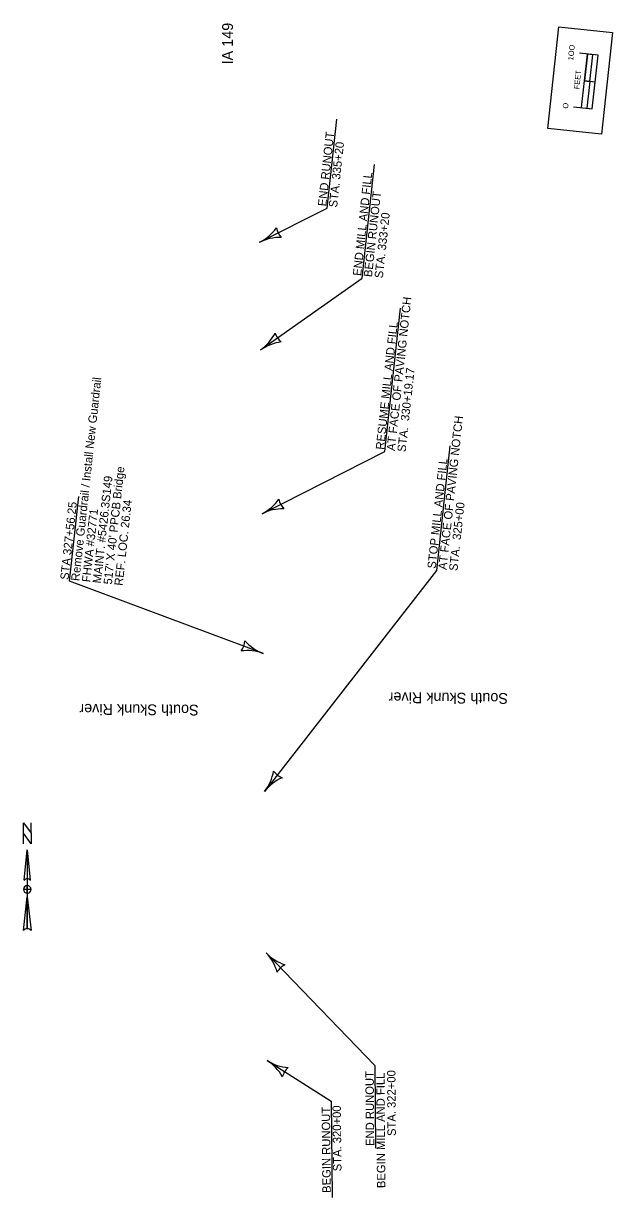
# Model space of a CAD drawing. Extents: x 23417754 to 23421386, y 6737896 to 6790956.
# Drawn here: x 23417793 to 23418886, y 6758227 to 6760407 of the extents above; entities that cross this region are included whole.
import ezdxf

# ---------------------------------------------------------------- set-up
doc = ezdxf.new("R2010")
doc.units = 0
for name, color, linetype in [('Curb', 7, 'Continuous'), ('Default', 7, 'Continuous'), ('dsnCellElements', 7, 'Continuous'), ('RasterAttachment', 7, 'Continuous'), ('TextAlignmentLrg', 7, 'Continuous')]:
    doc.layers.add(name, color=color, linetype=linetype)

msp = doc.modelspace()

# ---------------------------------------------------------------- linework, layer by layer
at = {"layer": 'Curb'}
msp.add_line((23418853.5, 6760298.7), (23418833.7, 6760300.8), dxfattribs=at)
msp.add_line((23418853.5, 6760298.7), (23418833.7, 6760300.8), dxfattribs=at)
for points in [[(23418765.8, 6760212.6), (23418786.2, 6760401.5), (23418885.6, 6760390.8), (23418865.2, 6760201.9)], [(23418865.2, 6760201.9), (23418765.8, 6760212.6), (23418786.2, 6760401.5), (23418885.6, 6760390.8)], [(23418843.5, 6760299.8), (23418848.9, 6760349.5), (23418839, 6760350.6), (23418833.7, 6760300.8)], [(23418848.2, 6760249), (23418853.5, 6760298.7), (23418843.5, 6760299.8), (23418838.2, 6760250.1)]]:
    msp.add_lwpolyline(points, close=True, dxfattribs=at)
for points in [[(23418813.4, 6760252.7), (23418848.2, 6760249), (23418858.9, 6760348.4), (23418824.1, 6760352.2)], [(23418828.3, 6760251.1), (23418839, 6760350.6)]]:
    msp.add_lwpolyline(points, dxfattribs=at)
at = {"layer": 'dsnCellElements'}
for points in [[(23418230.8, 6760001), (23418356.2, 6760064.6), (23418374, 6760229.5)], [(23418232.7, 6759801), (23418421, 6759934.6), (23418443.8, 6760145.8)], [(23418235.5, 6759496.8), (23418463.5, 6759612.4), (23418492.2, 6759878.4)], [(23418240.5, 6758981), (23418559.4, 6759391.5), (23418584.4, 6759623.1)], [(23418237.8, 6759237.3), (23417878.2, 6759371.3), (23417895.2, 6759528.9)], [(23418243, 6758681), (23418444.6, 6758471.6), (23418445.6, 6758318.3)], [(23418244.8, 6758481), (23418363.4, 6758405.6), (23418365.2, 6758226.7)]]:
    msp.add_lwpolyline(points, dxfattribs=at)
for centre, radius, start, end in [((23418192.4, 6760076.8), 85, 296.8818, 324.9543), ((23418294.4, 6760033.2), 32.8, 189.1485, 224.6152), ((23418269.3, 6759925.1), 85, 88.8094, 116.8818), ((23418183.5, 6759870.3), 85, 305.3584, 333.4309), ((23418290.8, 6759842.3), 32.8, 197.6251, 233.0918), ((23418281.9, 6759731.6), 85, 97.2859, 125.3584), ((23418197, 6759572.7), 85, 296.8818, 324.9543), ((23418299.1, 6759529.1), 32.8, 189.1485, 224.6152), ((23418273.9, 6759421), 85, 88.8093, 116.8818), ((23418170.7, 6759262.2), 32.8, 321.781, 357.2477), ((23418267.3, 6759316.9), 85, 221.4418, 249.5143), ((23418207.7, 6759157.6), 85, 69.5143, 97.5868), ((23418173.1, 6759033.3), 85, 322.1016, 350.1741), ((23418284, 6759037.3), 32.8, 214.3682, 249.8349), ((23418307.3, 6758928.8), 85, 114.0291, 142.1016), ((23418181.7, 6758622.1), 85, 15.8382, 43.9107), ((23418304.2, 6758740), 85, 223.9107, 251.9832), ((23418292.4, 6758629.7), 32.8, 116.1773, 151.644), ((23418199.2, 6758409.3), 85, 29.4531, 57.5256), ((23418290.5, 6758552.8), 85, 237.5256, 265.5981), ((23418305, 6758442.8), 32.8, 129.7923, 165.259)]:
    msp.add_arc(centre, radius, start, end, dxfattribs=at)
at = {"layer": 'TextAlignmentLrg'}
for p, q in [((23417799.8, 6758872.2), (23417805.4, 6758815.9)), ((23417799.8, 6758872.2), (23417799.8, 6758725.7)), ((23417794.2, 6758815.9), (23417794.2, 6758815.9)), ((23417794.4, 6758816.4), (23417795.4, 6758817.6)), ((23417792.8, 6758722.9), (23417799.8, 6758784.9)), ((23417799.8, 6758791.9), (23417799.8, 6758791.9))]:
    msp.add_line(p, q, dxfattribs=at)
msp.add_lwpolyline([(23417806.9, 6758883.5), (23417792.8, 6758903.2), (23417792.8, 6758922.9), (23417806.9, 6758903.2)], close=True, dxfattribs=at)
for points in [[(23417792.8, 6758883.5), (23417792.8, 6758922.9), (23417806.9, 6758903.2), (23417806.9, 6758922.9)], [(23417794.2, 6758815.9), (23417799.8, 6758872.2), (23417799.8, 6758818.7)], [(23417799.8, 6758791.9), (23417799.8, 6758799), (23417792.8, 6758799)], [(23417806.9, 6758799), (23417799.8, 6758799), (23417799.8, 6758806)], [(23417799.8, 6758725.7), (23417799.8, 6758784.9), (23417806.9, 6758722.9)]]:
    msp.add_lwpolyline(points, dxfattribs=at)
for centre, radius, start, end in [((23417799.8, 6758811.6), 7.04, 90.0204, 143.1257), ((23417799.8, 6758811.6), 7.04, 36.8481, 90.0218), ((23417799.8, 6758799), 7.04, 90, 180), ((23417799.8, 6758799), 7.04, 180, 270), ((23417799.8, 6758799), 7.04, 0, 90), ((23417799.8, 6758799), 7.04, 270, 360), ((23417799.8, 6758715.5), 10.2, 89.9894, 133.619), ((23417799.8, 6758715.5), 10.2, 46.4021, 90.0006)]:
    msp.add_arc(centre, radius, start, end, dxfattribs=at)

# ---------------------------------------------------------------- texts
at = {"layer": 'Curb'}
for s, p in [('1OO', (23418812.6, 6760338.5)), ('1OO', (23418812.6, 6760338.5)), ('FEET', (23418823.9, 6760284.9)), ('O', (23418802.9, 6760248.9)), ('O', (23418802.9, 6760248.9))]:
    msp.add_text(s, height=10, rotation=83.835, dxfattribs=at).set_placement(p)
at = {"layer": 'Default'}
msp.add_text('IA 149', height=20, rotation=89.8466, dxfattribs=at).set_placement((23418181.2, 6760331.4))
at = {"layer": 'dsnCellElements'}
for s, height, rotation, p in [('END RUNOUT', 15.6, 83.835, (23418354.4, 6760067.3)), ('STA. 335+20', 15.605, 83.835, (23418374.5, 6760065.1)), ('END MILL AND FILL', 15.605, 83.835, (23418419.2, 6759938)), ('BEGIN RUNOUT', 15.605, 83.835, (23418439.3, 6759935.8)), ('STA. 333+20', 15.605, 83.835, (23418459.4, 6759933.7)), ('AT FACE OF PAVING NOTCH', 15.605, 83.835, (23418481.8, 6759613)), ('RESUME MILL AND FILL', 15.605, 83.835, (23418461.7, 6759615.2)), ('STA.  330+19.17', 15.605, 83.835, (23418501.8, 6759610.9)), ('Remove Guardrail / Install New Guardrail', 15.605, 83.835, (23417896.4, 6759371.2)), ('AT FACE OF PAVING NOTCH', 15.605, 83.835, (23418577.6, 6759392)), ("517' X 40' PPCB Bridge", 15.605, 83.835, (23417956.6, 6759364.7)), ('STOP MILL AND FILL', 15.605, 83.835, (23418557.5, 6759394.2)), ('MAINT. #5426.3S149', 15.605, 83.835, (23417936.5, 6759366.8)), ('STA 327+56.25', 15.605, 83.835, (23417876.3, 6759373.4)), ('REF. LOC. 26.34', 15.605, 83.835, (23417976.7, 6759362.5)), ('STA.  325+00', 15.605, 83.835, (23418597.7, 6759389.9)), ('FHWA #32771', 15.605, 83.835, (23417916.5, 6759369)), ('END RUNOUT', 15.6, 90.3848, (23418443.5, 6758322.5)), ('BEGIN MILL AND FILL', 15.605, 90.3848, (23418464.2, 6758244.2)), ('STA. 322+00', 15.605, 90.3848, (23418483.7, 6758340.9)), ('BEGIN RUNOUT', 15.605, 90.5725, (23418363, 6758235.3)), ('STA. 320+00', 15.605, 90.5725, (23418382.8, 6758275.4))]:
    msp.add_text(s, height=height, rotation=rotation, dxfattribs=at).set_placement(p)
at = {"layer": 'RasterAttachment'}
for p in [(23418691.8, 6759163.6), (23418117.9, 6759142)]:
    msp.add_text('South Skunk River', height=20, rotation=179.5786, dxfattribs=at).set_placement(p)

doc.saveas('drawing.dxf')
